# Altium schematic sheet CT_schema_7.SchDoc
size 278 x 170 mm
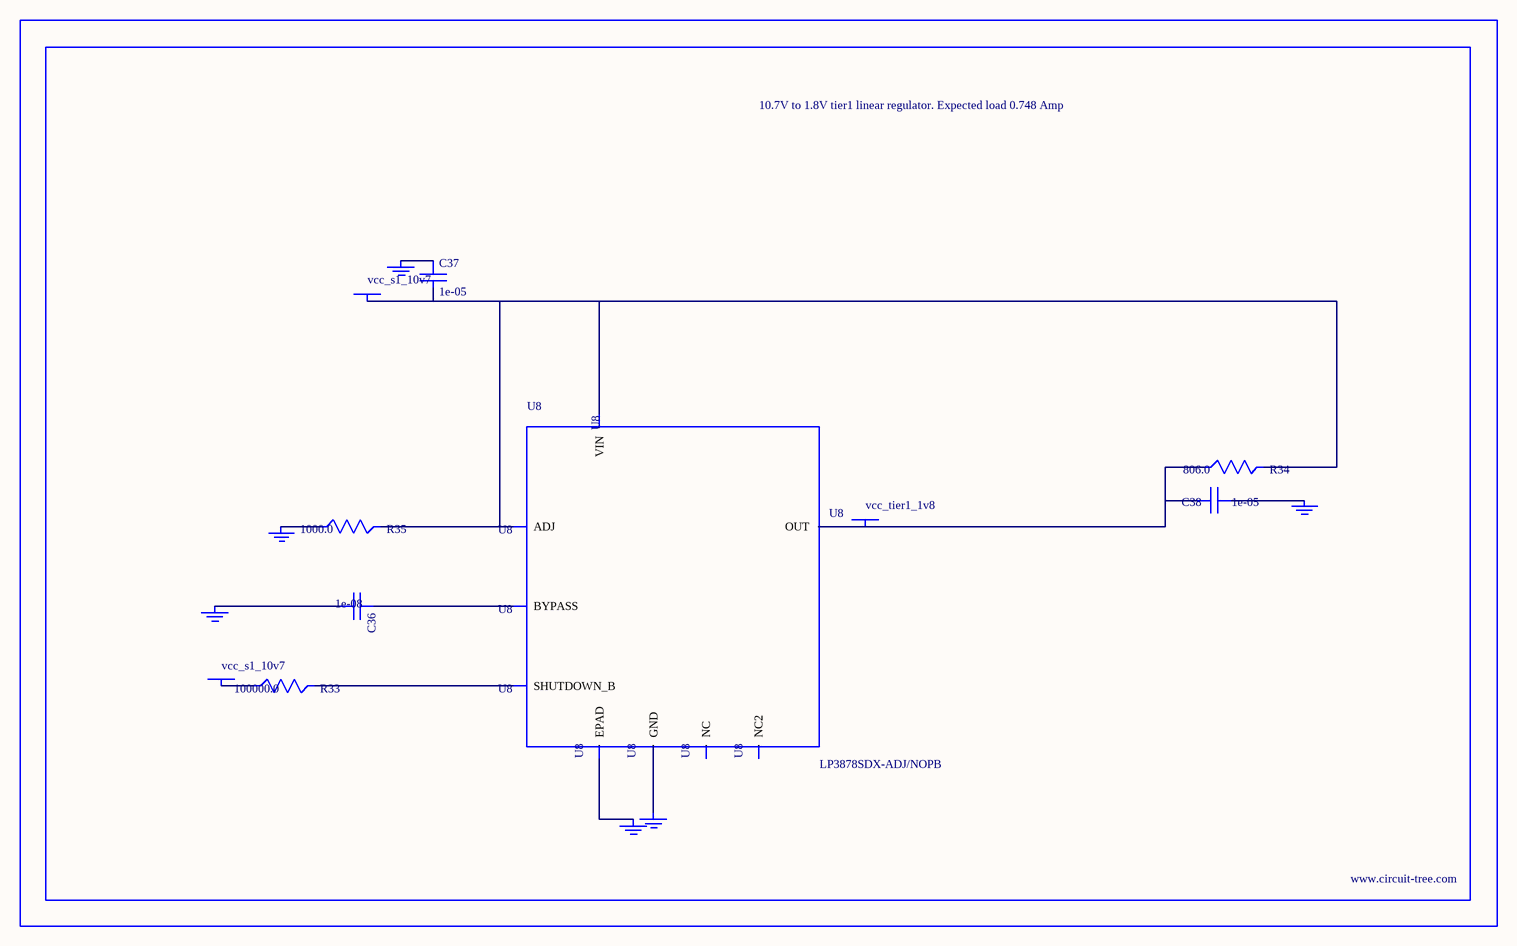
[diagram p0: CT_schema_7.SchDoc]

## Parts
BORDER6  (no value)
C36  1e-08  [C0402]
C37  1e-05  [C1206]
C38  1e-05  [C0805]
GND_INSTANCE_6_0  (no value)
GND_INSTANCE_6_1  (no value)
GND_INSTANCE_6_2  (no value)
GND_INSTANCE_6_3  (no value)
GND_INSTANCE_6_4  (no value)
GND_INSTANCE_6_5  (no value)
POWER_INSTANCE_6_0  vcc_s1_10v7
POWER_INSTANCE_6_1  vcc_s1_10v7
POWER_INSTANCE_6_2  vcc_tier1_1v8
R33  100000.0  [R0603]
R34  806.0  [R0603]
R35  1000.0  [R0603]
U8  LP3878SDX-ADJ/NOPB  [WSON-8]

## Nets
NetC36_1: C36.1 U8.1(BYPASS)
NetC36_2: C36.2 GND_INSTANCE_6_0.0(GND)
NetC37_1: C37.1 GND_INSTANCE_6_1.0(GND)
NetC37_2: C37.2 POWER_INSTANCE_6_0.0(PWR) R34.2 R35.2 U8.4(VIN) U8.6(ADJ)
NetC38_1: C38.1 GND_INSTANCE_6_2.0(GND)
NetC38_2: C38.2 POWER_INSTANCE_6_2.0(PWR) R34.1 U8.5(OUT)
NetGND_INSTANCE_6_3_0: GND_INSTANCE_6_3.0(GND) R35.1
NetGND_INSTANCE_6_4_0: GND_INSTANCE_6_4.0(GND) U8.PAD(EPAD)
NetGND_INSTANCE_6_5_0: GND_INSTANCE_6_5.0(GND) U8.3(GND)
NetPOWER_INSTANCE_6_1_0: POWER_INSTANCE_6_1.0(PWR) R33.1
NetR33_2: R33.2 U8.8(SHUTDOWN_B)

Not connected (* = marked no-connect by the designer): U8 2(NC) 7(NC2)

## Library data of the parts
BORDER6 = BORDER_PAGE6
C36 = C0402C103K3RAC
C37 = C1206C106K3RACTU
C38 = GRM219R60J106ME19D
GND_INSTANCE_6_0-GND_INSTANCE_6_5 = GND
POWER_INSTANCE_6_0-POWER_INSTANCE_6_2 = PWR
R33 = RC0603JR-07100KL
R34 = ERJ-3EKF8060V
R35 = RC0603JR-071KL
